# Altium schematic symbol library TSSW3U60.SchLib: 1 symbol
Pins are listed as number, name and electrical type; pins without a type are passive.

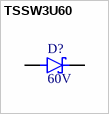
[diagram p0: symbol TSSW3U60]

## TSSW3U60
designator D?, comment 60V
DIODE SCHOTTKY 60V 3A SOD123W; PartNumber: TSSW3U60; MF: {'manufacturer': u'Taiwan Semiconductor Corporation'}
footprint SODFL3718X102N
pins: A, C K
